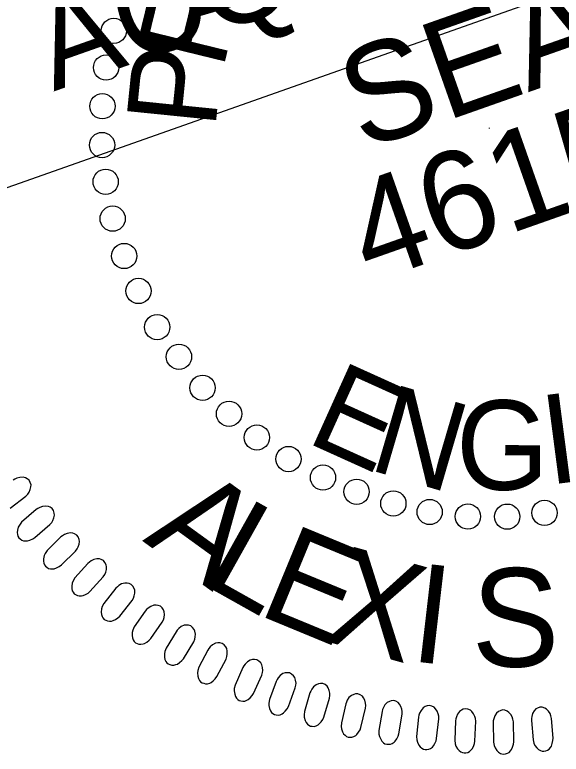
# Model space of a CAD drawing. Extents: x 473817 to 475769, y 501102 to 502694.
# Drawn here: x 475352.37 to 475387, y 502516.17 to 502563 of the extents above; entities that cross this region are included whole.
import ezdxf

# ---------------------------------------------------------------- set-up
doc = ezdxf.new("R2010")
doc.units = 0
doc.layers.add('Sheet PE Seal Cell', color=7, linetype='Continuous')
doc.layers.add('Sheet Sticker Incomplete CELL', color=7, linetype='Continuous')

msp = doc.modelspace()

# ---------------------------------------------------------------- linework, layer by layer
at = {"layer": 'Sheet PE Seal Cell'}
msp.add_line((475382.428, 502555.843), (475382.443, 502555.799), dxfattribs=at)
msp.add_lwpolyline([(475352.074, 502531.758), (475353.077, 502532.515), (475353.197, 502532.636), (475353.281, 502532.757), (475353.353, 502532.924), (475353.396, 502533.098), (475353.401, 502533.224), (475353.352, 502533.385), (475353.277, 502533.516), (475353.155, 502533.611), (475353.052, 502533.664), (475352.896, 502533.704), (475352.689, 502533.696), (475352.505, 502533.64), (475352.384, 502533.585), (475352.272, 502533.518)], dxfattribs=at)
for points in [[(475353.732, 502531.661), (475352.805, 502530.856), (475352.664, 502530.683), (475352.593, 502530.553), (475352.539, 502530.357), (475352.52, 502530.211), (475352.533, 502530.074), (475352.572, 502529.97), (475352.63, 502529.872), (475352.718, 502529.801), (475352.82, 502529.73), (475352.933, 502529.69), (475353.077, 502529.677), (475353.177, 502529.684), (475353.334, 502529.731), (475353.508, 502529.804), (475353.644, 502529.891), (475354.597, 502530.71), (475354.711, 502530.838), (475354.786, 502530.964), (475354.848, 502531.136), (475354.88, 502531.312), (475354.876, 502531.438), (475354.818, 502531.596), (475354.735, 502531.722), (475354.607, 502531.808), (475354.501, 502531.854), (475354.342, 502531.885), (475354.136, 502531.863), (475353.956, 502531.797), (475353.839, 502531.734)], [(475355.298, 502529.924), (475354.424, 502529.062), (475354.295, 502528.881), (475354.231, 502528.746), (475354.19, 502528.547), (475354.18, 502528.401), (475354.202, 502528.265), (475354.247, 502528.162), (475354.311, 502528.068), (475354.404, 502528.003), (475354.51, 502527.939), (475354.626, 502527.906), (475354.77, 502527.902), (475354.869, 502527.915), (475355.023, 502527.972), (475355.193, 502528.056), (475355.322, 502528.152), (475356.222, 502529.029), (475356.327, 502529.164), (475356.395, 502529.294), (475356.445, 502529.469), (475356.467, 502529.648), (475356.455, 502529.773), (475356.387, 502529.927), (475356.296, 502530.048), (475356.163, 502530.125), (475356.053, 502530.165), (475355.894, 502530.186), (475355.689, 502530.151), (475355.514, 502530.074), (475355.401, 502530.004)], [(475357, 502528.245), (475356.182, 502527.33), (475356.064, 502527.143), (475356.01, 502527.003), (475355.98, 502526.802), (475355.98, 502526.655), (475356.01, 502526.522), (475356.062, 502526.422), (475356.132, 502526.332), (475356.229, 502526.273), (475356.339, 502526.215), (475356.456, 502526.19), (475356.601, 502526.195), (475356.698, 502526.214), (475356.848, 502526.281), (475357.012, 502526.375), (475357.136, 502526.478), (475357.979, 502527.411), (475358.075, 502527.552), (475358.134, 502527.686), (475358.173, 502527.865), (475358.183, 502528.043), (475358.164, 502528.168), (475358.087, 502528.317), (475357.988, 502528.432), (475357.85, 502528.501), (475357.739, 502528.534), (475357.578, 502528.545), (475357.376, 502528.497), (475357.206, 502528.409), (475357.097, 502528.332)], [(475358.781, 502526.673), (475358.022, 502525.709), (475357.915, 502525.514), (475357.87, 502525.372), (475357.853, 502525.169), (475357.862, 502525.023), (475357.901, 502524.89), (475357.958, 502524.794), (475358.034, 502524.709), (475358.135, 502524.656), (475358.247, 502524.606), (475358.367, 502524.588), (475358.51, 502524.601), (475358.606, 502524.627), (475358.752, 502524.703), (475358.91, 502524.807), (475359.026, 502524.918), (475359.809, 502525.902), (475359.897, 502526.048), (475359.947, 502526.187), (475359.976, 502526.367), (475359.974, 502526.546), (475359.947, 502526.669), (475359.86, 502526.813), (475359.755, 502526.921), (475359.613, 502526.982), (475359.5, 502527.008), (475359.338, 502527.008), (475359.14, 502526.949), (475358.975, 502526.849), (475358.872, 502526.766)], [(475360.641, 502525.235), (475359.944, 502524.225), (475359.851, 502524.023), (475359.814, 502523.879), (475359.81, 502523.675), (475359.828, 502523.53), (475359.875, 502523.401), (475359.938, 502523.309), (475360.02, 502523.228), (475360.123, 502523.181), (475360.239, 502523.138), (475360.359, 502523.127), (475360.502, 502523.151), (475360.596, 502523.182), (475360.737, 502523.267), (475360.888, 502523.381), (475360.997, 502523.499), (475361.716, 502524.529), (475361.794, 502524.682), (475361.836, 502524.822), (475361.853, 502525.005), (475361.84, 502525.183), (475361.806, 502525.304), (475361.71, 502525.443), (475361.598, 502525.544), (475361.453, 502525.595), (475361.338, 502525.614), (475361.177, 502525.605), (475360.983, 502525.532), (475360.825, 502525.423), (475360.727, 502525.333)], [(475362.591, 502523.927), (475361.959, 502522.876), (475361.878, 502522.669), (475361.85, 502522.522), (475361.859, 502522.319), (475361.886, 502522.175), (475361.941, 502522.049), (475362.01, 502521.961), (475362.096, 502521.886), (475362.202, 502521.846), (475362.321, 502521.809), (475362.441, 502521.806), (475362.582, 502521.839), (475362.674, 502521.876), (475362.809, 502521.97), (475362.952, 502522.093), (475363.054, 502522.217), (475363.708, 502523.291), (475363.776, 502523.448), (475363.809, 502523.591), (475363.814, 502523.773), (475363.791, 502523.951), (475363.748, 502524.07), (475363.644, 502524.202), (475363.526, 502524.296), (475363.378, 502524.338), (475363.262, 502524.349), (475363.102, 502524.33), (475362.912, 502524.246), (475362.762, 502524.127), (475362.67, 502524.031)], [(475364.603, 502522.76), (475364.039, 502521.67), (475363.971, 502521.459), (475363.953, 502521.311), (475363.974, 502521.108), (475364.011, 502520.967), (475364.073, 502520.844), (475364.148, 502520.76), (475364.238, 502520.691), (475364.347, 502520.657), (475364.467, 502520.629), (475364.587, 502520.634), (475364.726, 502520.675), (475364.816, 502520.717), (475364.945, 502520.819), (475365.08, 502520.951), (475365.174, 502521.082), (475365.758, 502522.195), (475365.817, 502522.356), (475365.841, 502522.5), (475365.835, 502522.683), (475365.8, 502522.859), (475365.75, 502522.974), (475365.638, 502523.1), (475365.514, 502523.186), (475365.363, 502523.219), (475365.247, 502523.223), (475365.089, 502523.193), (475364.905, 502523.098), (475364.762, 502522.969), (475364.676, 502522.868)], [(475366.831, 502521.66), (475366.336, 502520.537), (475366.282, 502520.322), (475366.274, 502520.173), (475366.308, 502519.972), (475366.352, 502519.832), (475366.423, 502519.714), (475366.502, 502519.636), (475366.597, 502519.572), (475366.707, 502519.546), (475366.829, 502519.525), (475366.949, 502519.537), (475367.085, 502519.586), (475367.171, 502519.635), (475367.294, 502519.744), (475367.421, 502519.885), (475367.506, 502520.021), (475368.02, 502521.169), (475368.067, 502521.332), (475368.082, 502521.479), (475368.065, 502521.661), (475368.019, 502521.833), (475367.962, 502521.946), (475367.843, 502522.064), (475367.713, 502522.143), (475367.561, 502522.166), (475367.445, 502522.163), (475367.288, 502522.123), (475367.111, 502522.016), (475366.976, 502521.879), (475366.897, 502521.772)], [(475368.934, 502520.779), (475368.51, 502519.627), (475368.47, 502519.408), (475368.47, 502519.259), (475368.517, 502519.062), (475368.571, 502518.925), (475368.648, 502518.811), (475368.733, 502518.737), (475368.831, 502518.68), (475368.942, 502518.661), (475369.065, 502518.648), (475369.184, 502518.667), (475369.317, 502518.725), (475369.401, 502518.779), (475369.516, 502518.896), (475369.634, 502519.044), (475369.71, 502519.186), (475370.151, 502520.363), (475370.188, 502520.53), (475370.194, 502520.677), (475370.165, 502520.857), (475370.109, 502521.026), (475370.044, 502521.136), (475369.918, 502521.245), (475369.784, 502521.316), (475369.63, 502521.33), (475369.514, 502521.319), (475369.361, 502521.269), (475369.191, 502521.152), (475369.064, 502521.006), (475368.992, 502520.895)], [(475371.079, 502520.05), (475370.729, 502518.874), (475370.702, 502518.654), (475370.712, 502518.505), (475370.771, 502518.31), (475370.834, 502518.177), (475370.918, 502518.069), (475371.007, 502518), (475371.109, 502517.949), (475371.222, 502517.936), (475371.345, 502517.931), (475371.462, 502517.958), (475371.591, 502518.024), (475371.671, 502518.083), (475371.778, 502518.208), (475371.887, 502518.363), (475371.954, 502518.509), (475372.32, 502519.711), (475372.347, 502519.88), (475372.343, 502520.027), (475372.304, 502520.205), (475372.236, 502520.371), (475372.166, 502520.475), (475372.032, 502520.578), (475371.894, 502520.64), (475371.74, 502520.644), (475371.625, 502520.626), (475371.475, 502520.567), (475371.313, 502520.438), (475371.196, 502520.285), (475371.131, 502520.169)], [(475373.343, 502519.35), (475373.067, 502518.154), (475373.054, 502517.932), (475373.073, 502517.784), (475373.144, 502517.593), (475373.214, 502517.465), (475373.306, 502517.363), (475373.398, 502517.299), (475373.504, 502517.256), (475373.617, 502517.249), (475373.741, 502517.251), (475373.856, 502517.286), (475373.98, 502517.36), (475374.057, 502517.425), (475374.156, 502517.555), (475374.254, 502517.716), (475374.312, 502517.867), (475374.602, 502519.09), (475374.618, 502519.26), (475374.606, 502519.406), (475374.554, 502519.582), (475374.477, 502519.743), (475374.399, 502519.842), (475374.261, 502519.937), (475374.119, 502519.989), (475373.964, 502519.983), (475373.851, 502519.959), (475373.705, 502519.891), (475373.551, 502519.752), (475373.444, 502519.592), (475373.386, 502519.473)], [(475375.65, 502518.874), (475375.45, 502517.664), (475375.451, 502517.442), (475375.479, 502517.295), (475375.562, 502517.11), (475375.64, 502516.985), (475375.738, 502516.888), (475375.834, 502516.832), (475375.943, 502516.794), (475376.056, 502516.796), (475376.179, 502516.805), (475376.292, 502516.847), (475376.411, 502516.929), (475376.483, 502516.997), (475376.574, 502517.134), (475376.663, 502517.302), (475376.711, 502517.455), (475376.923, 502518.694), (475376.928, 502518.865), (475376.907, 502519.01), (475376.845, 502519.182), (475376.757, 502519.338), (475376.674, 502519.433), (475376.529, 502519.517), (475376.385, 502519.561), (475376.231, 502519.546), (475376.119, 502519.514), (475375.978, 502519.437), (475375.832, 502519.289), (475375.736, 502519.123), (475375.686, 502519)], [(475377.96, 502518.516), (475377.836, 502517.296), (475377.851, 502517.074), (475377.889, 502516.929), (475377.984, 502516.749), (475378.069, 502516.63), (475378.173, 502516.54), (475378.272, 502516.489), (475378.383, 502516.458), (475378.496, 502516.467), (475378.618, 502516.484), (475378.728, 502516.533), (475378.842, 502516.622), (475378.91, 502516.695), (475378.992, 502516.837), (475379.07, 502517.01), (475379.108, 502517.166), (475379.243, 502518.416), (475379.237, 502518.587), (475379.206, 502518.73), (475379.134, 502518.898), (475379.036, 502519.048), (475378.947, 502519.137), (475378.797, 502519.213), (475378.65, 502519.248), (475378.498, 502519.223), (475378.388, 502519.184), (475378.252, 502519.098), (475378.116, 502518.942), (475378.031, 502518.769), (475377.989, 502518.644)], [(475380.302, 502518.273), (475380.255, 502517.047), (475380.284, 502516.826), (475380.33, 502516.684), (475380.436, 502516.51), (475380.529, 502516.397), (475380.638, 502516.313), (475380.741, 502516.269), (475380.853, 502516.245), (475380.965, 502516.261), (475381.086, 502516.286), (475381.193, 502516.341), (475381.301, 502516.438), (475381.364, 502516.515), (475381.437, 502516.662), (475381.503, 502516.839), (475381.532, 502516.997), (475381.588, 502518.253), (475381.572, 502518.423), (475381.532, 502518.564), (475381.449, 502518.727), (475381.342, 502518.871), (475381.248, 502518.955), (475381.093, 502519.021), (475380.944, 502519.046), (475380.794, 502519.011), (475380.687, 502518.965), (475380.556, 502518.871), (475380.431, 502518.706), (475380.356, 502518.529), (475380.322, 502518.401)], [(475382.685, 502518.156), (475382.715, 502516.93), (475382.758, 502516.711), (475382.813, 502516.573), (475382.929, 502516.406), (475383.029, 502516.299), (475383.144, 502516.222), (475383.249, 502516.185), (475383.362, 502516.167), (475383.473, 502516.19), (475383.592, 502516.223), (475383.695, 502516.285), (475383.797, 502516.388), (475383.855, 502516.469), (475383.919, 502516.62), (475383.974, 502516.801), (475383.993, 502516.961), (475383.97, 502518.217), (475383.943, 502518.387), (475383.894, 502518.525), (475383.801, 502518.682), (475383.686, 502518.819), (475383.586, 502518.896), (475383.428, 502518.952), (475383.278, 502518.969), (475383.129, 502518.925), (475383.026, 502518.872), (475382.901, 502518.77), (475382.787, 502518.598), (475382.723, 502518.416), (475382.697, 502518.286)], [(475385.109, 502518.297), (475385.216, 502517.075), (475385.272, 502516.861), (475385.336, 502516.725), (475385.463, 502516.566), (475385.569, 502516.465), (475385.688, 502516.396), (475385.795, 502516.365), (475385.909, 502516.355), (475386.018, 502516.385), (475386.136, 502516.426), (475386.234, 502516.493), (475386.33, 502516.602), (475386.383, 502516.686), (475386.436, 502516.842), (475386.48, 502517.026), (475386.489, 502517.187), (475386.387, 502518.439), (475386.349, 502518.606), (475386.292, 502518.741), (475386.189, 502518.892), (475386.066, 502519.022), (475385.962, 502519.093), (475385.8, 502519.139), (475385.65, 502519.145), (475385.503, 502519.092), (475385.404, 502519.034), (475385.286, 502518.923), (475385.182, 502518.744), (475385.13, 502518.559), (475385.112, 502518.428)]]:
    msp.add_lwpolyline(points, close=True, dxfattribs=at)
for centre in [(475358.647, 502561.979), (475358.158, 502559.653), (475357.923, 502557.205), (475357.902, 502554.747), (475358.13, 502552.421), (475358.573, 502550.085), (475359.305, 502547.719), (475360.212, 502545.504), (475361.397, 502543.218), (475362.776, 502541.339), (475364.271, 502539.373), (475365.949, 502537.726), (475367.717, 502536.225), (475369.718, 502534.86), (475371.904, 502533.687), (475374.035, 502532.79), (475376.364, 502532.048), (475378.666, 502531.507), (475381.088, 502531.22), (475383.582, 502531.212), (475385.945, 502531.453)]:
    msp.add_circle(centre, 0.801, dxfattribs=at)
at = {"layer": 'Sheet Sticker Incomplete CELL'}
msp.add_lwpolyline([(475264.194, 502521.136), (475256.379, 502543.298), (475395.013, 502592.182), (475402.828, 502570.019)], close=True, dxfattribs=at)

# ---------------------------------------------------------------- texts
at = {"layer": 'Sheet PE Seal Cell'}
for s, height, rotation, p in [('SEAL', 6.2363, 19.4044, (475374.413, 502554.389)), ('R', 5.669, 76.2906, (475365.545, 502559.438)), ('P', 5.669, 84.2304, (475365.072, 502555.706)), ('46155', 6.2363, 19.4044, (475374.885, 502545.989)), ('E', 5.669, 335.6886, (475370.725, 502535.976)), ('N', 5.669, 343.6284, (475374.664, 502534.232)), ('I', 5.669, 7.4478, (475386.18, 502533.215)), ('G', 5.669, 359.508, (475380.31, 502532.937)), ('A', 6.236, 324.1064, (475360.426, 502529.692)), ('L', 6.236, 330.7261, (475364.046, 502527.067)), ('E', 6.236, 337.5718, (475367.629, 502525.063)), ('X', 6.236, 344.4174, (475371.826, 502523.39)), ('I', 6.236, 353.3647, (475377.322, 502522.083)), ('S', 6.236, 0.2104, (475381.333, 502521.701))]:
    msp.add_text(s, height=height, rotation=rotation, dxfattribs=at).set_placement(p)
at = {"layer": 'Sheet Sticker Incomplete CELL'}
for s, height, p in [('INCOMPLETE PLANS', 11.52, (475268.744, 502535.146)), ('DO NOT USE FOR R/W ACQUISITION', 5.76, (475274.12, 502529.672))]:
    msp.add_text(s, height=height, rotation=19.423, dxfattribs=at).set_placement(p)

doc.saveas('drawing.dxf')
